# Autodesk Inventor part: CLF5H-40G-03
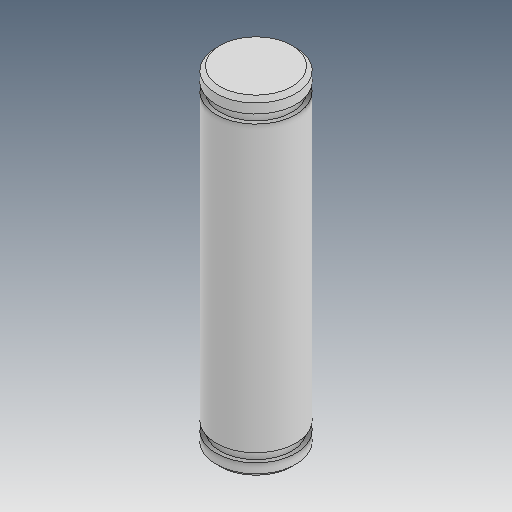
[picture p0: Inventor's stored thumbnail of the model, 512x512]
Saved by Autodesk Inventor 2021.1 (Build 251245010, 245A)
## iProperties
Created: 2013-04
Part Number: CLF5H-40G-03
Material: Ogólny
Document SubType Name: Modeling
Designer: user
Density: 1 g/cm^3
Appearance: Domyślna
Author: user
Revision Number: ÈÎºÎ
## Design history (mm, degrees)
feature "Ðý×ª1"
node "Bryła1"
